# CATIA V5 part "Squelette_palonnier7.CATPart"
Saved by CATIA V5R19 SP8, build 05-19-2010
Part number: Squelette_palonnier7
Bounding box of the stored display mesh (mm): x 20 to 40, y 30 to 30, z -1.3 to 30
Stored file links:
  G:\EU_thinkMotion\CFAO_2010\MMS_groupe2\MMS_groupe2\A reprendre\jcauchy\Squelette_palonnier7.CATPart
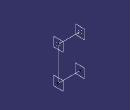
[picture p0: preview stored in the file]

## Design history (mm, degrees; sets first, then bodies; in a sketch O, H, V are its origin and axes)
Parameters
  Longueurfixation_palonnier7 = 20 mm
  Longueurpalonnier_palonnier7 = 31.3 mm
Set1
  Point1: (20, 30, 30)
  Point2: (40, 30, 30)
  Line1: type PtPt, FirstPoint Point1, SecondPoint Point2
  Plane1: type Normal, Curve Line1, RefPoint Point1
  Plane2: type Normal, Curve Line1, RefPoint Point2
  Point3: type OnCurve, Support Line1, Length 20 {= Longueurfixation_palonnier7}
  Line2: type Angle, RefPoint Point3, Curve Line1, Support zx-plane, Start 0, End 31.3, Angle 90
  Line3: type Normal, RefPoint vertex of Line2, RefSkin Plane1, Start -20 {= -Longueurfixation_palonnier7}, End 0
  Plane3: type Normal, Curve Line3, RefPoint vertex of Line3
  Plane4: type Normal, Curve Line3, RefPoint vertex of Line3
Body1 (main body)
